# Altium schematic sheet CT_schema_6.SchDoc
size 405 x 220 mm
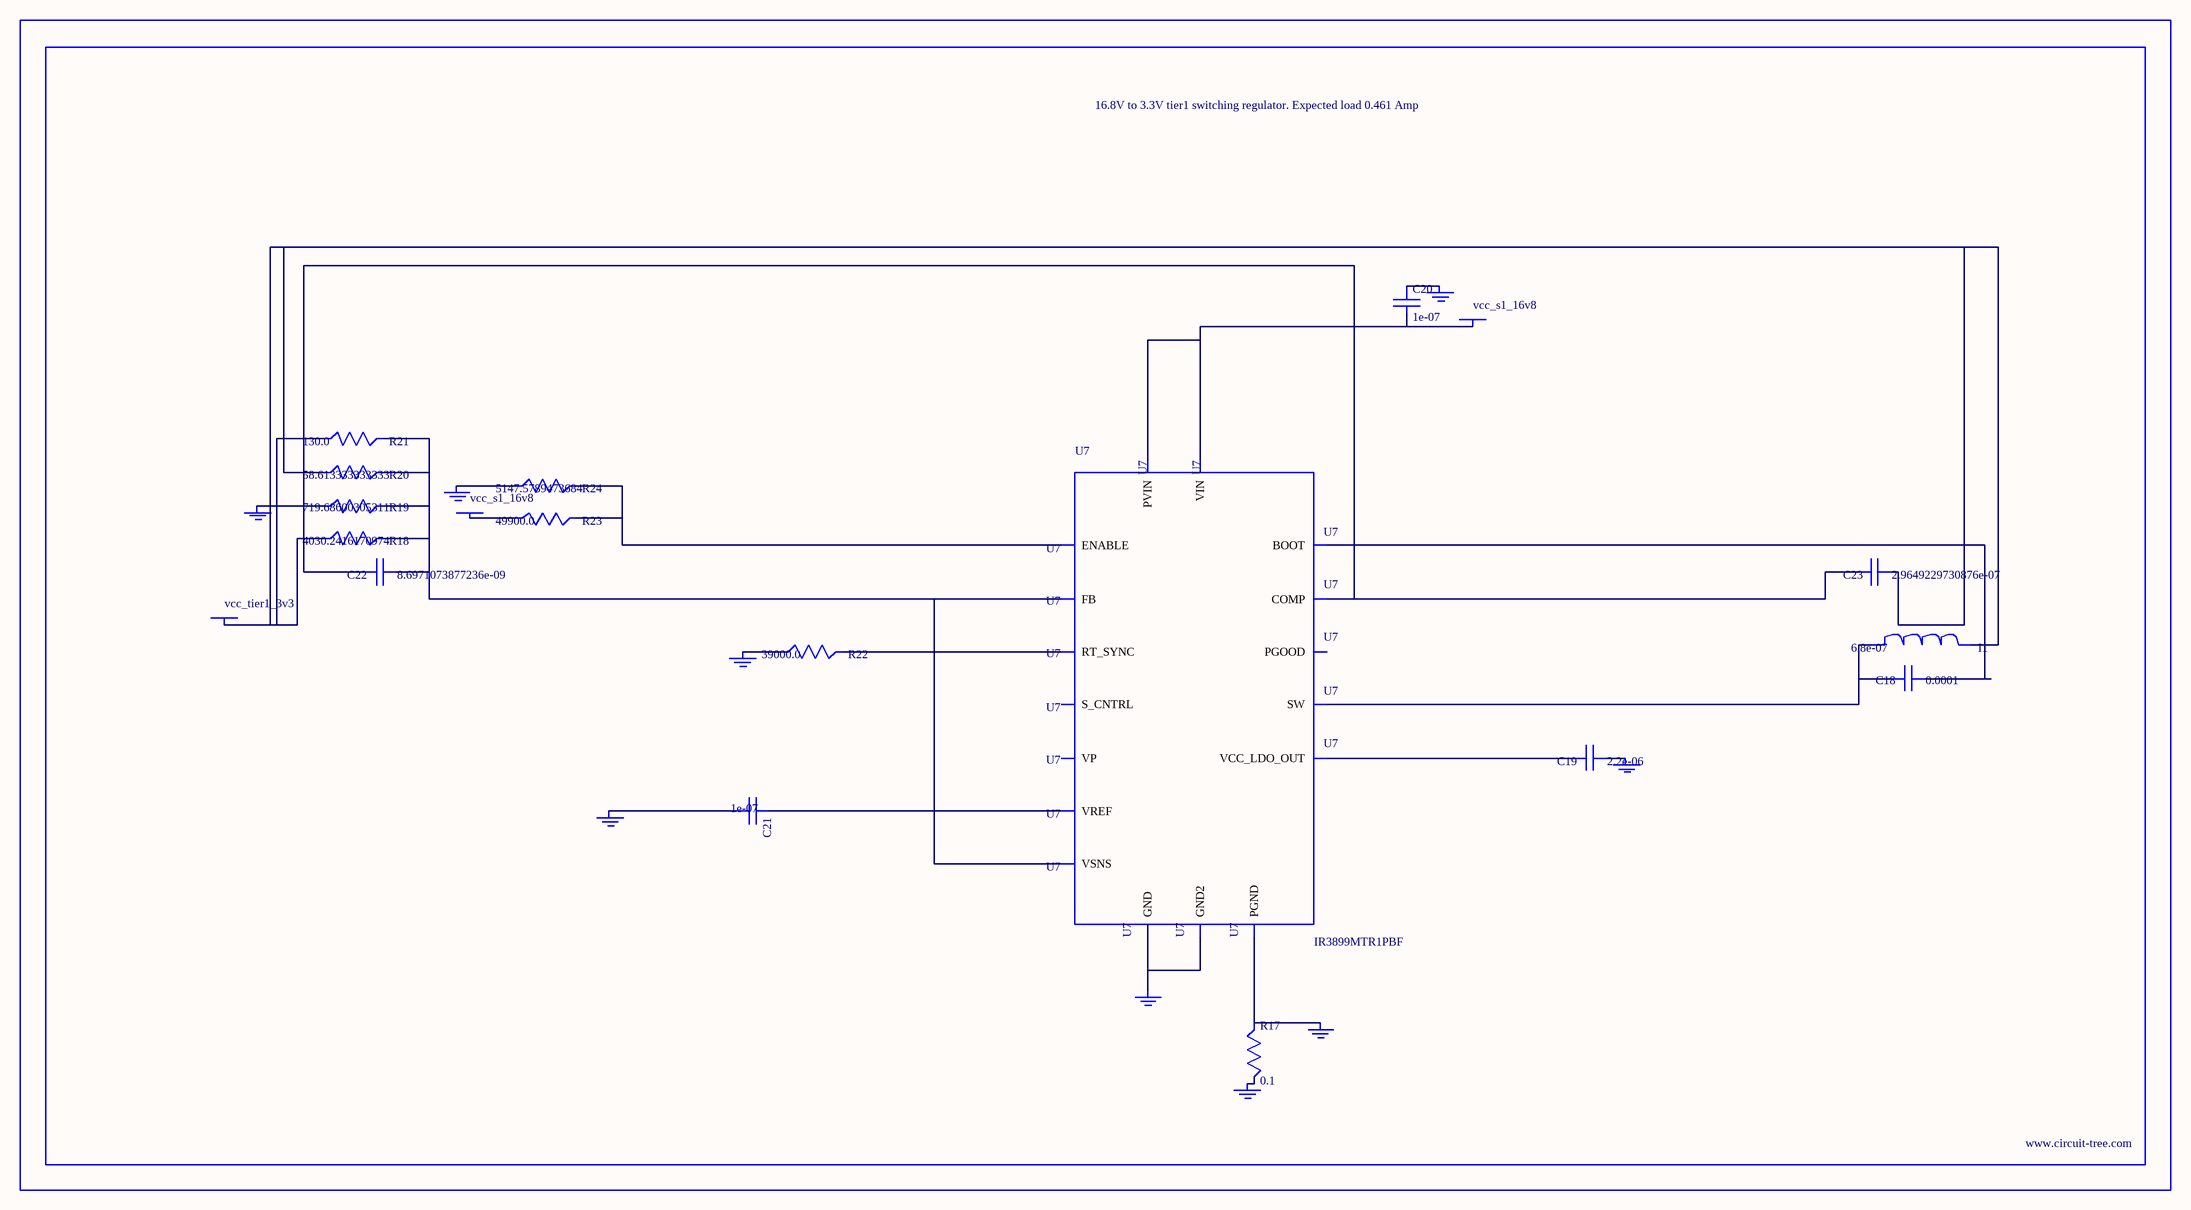
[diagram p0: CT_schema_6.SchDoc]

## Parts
BORDER5  (no value)
C18  0.0001  [C1210]
C19  2.2e-06  [C0603]
C20  1e-07  [C0402]
C21  1e-07  [C0402]
C22  8.6971073877236e-09  [R0603]
C23  2.9649229730876e-07  [R0603]
GND_INSTANCE_5_0  (no value)
GND_INSTANCE_5_1  (no value)
GND_INSTANCE_5_2  (no value)
GND_INSTANCE_5_3  (no value)
GND_INSTANCE_5_4  (no value)
GND_INSTANCE_5_5  (no value)
GND_INSTANCE_5_6  (no value)
GND_INSTANCE_5_7  (no value)
GND_INSTANCE_5_8  (no value)
I1  6.8e-07  [IND25X25CZ]
POWER_INSTANCE_5_0  vcc_s1_16v8
POWER_INSTANCE_5_1  vcc_s1_16v8
POWER_INSTANCE_5_2  vcc_tier1_3v3
R17  0.1  [R0603]
R18  4030.2416170974  [R0603]
R19  719.68600305311  [R0603]
R20  58.613333333333  [R0603]
R21  130.0  [R0603]
R22  39000.0  [R0603]
R23  49900.0  [R0603]
R24  5147.5789473684  [R0603]
U7  IR3899MTR1PBF  [IR3899MTR1PBF]

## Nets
NetC18_1: C18.1 U7.14(BOOT)
NetC18_2: C18.2 I1.1 U7.12(SW)
NetC19_1: C19.1 GND_INSTANCE_5_4.0(GND)
NetC19_2: C19.2 U7.10(VCC_LDO_OUT)
NetC20_1: C20.1 GND_INSTANCE_5_3.0(GND)
NetC20_2: C20.2 POWER_INSTANCE_5_0.0(PWR) U7.9(VIN) U7.13(PVIN)
NetC21_1: C21.1 U7.2(VREF)
NetC21_2: C21.2 GND_INSTANCE_5_1.0(GND)
NetC22_1: C22.1 R18.2 R19.2 R20.2 R21.2 U7.1(FB) U7.8(VSNS)
NetC22_2: C22.2 C23.2 U7.3(COMP)
NetC23_1: C23.1 I1.2 POWER_INSTANCE_5_2.0(PWR) R18.1 R20.1 R21.1
NetGND_INSTANCE_5_0_0: GND_INSTANCE_5_0.0(GND) R19.1
NetGND_INSTANCE_5_2_0: GND_INSTANCE_5_2.0(GND) R22.1
NetGND_INSTANCE_5_5_0: GND_INSTANCE_5_5.0(GND) R17.2
NetGND_INSTANCE_5_6_0: GND_INSTANCE_5_6.0(GND) R17.1 U7.11(PGND)
NetGND_INSTANCE_5_7_0: GND_INSTANCE_5_7.0(GND) R24.1
NetGND_INSTANCE_5_8_0: GND_INSTANCE_5_8.0(GND) U7.4(GND) U7.17(GND2)
NetPOWER_INSTANCE_5_1_0: POWER_INSTANCE_5_1.0(PWR) R23.1
NetR22_2: R22.2 U7.5(RT_SYNC)
NetR23_2: R23.2 R24.2 U7.15(ENABLE)

Not connected (* = marked no-connect by the designer): U7 6(S_CNTRL) 7(PGOOD) 16(VP)

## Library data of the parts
BORDER5 = BORDER_PAGE5
C18 = GRM32ER61A107ME20L
C19 = C0603C225K8RACTU
C20 C21 = C0402C104K3RACTU
C22 = C22
C23 = C23
GND_INSTANCE_5_0-GND_INSTANCE_5_8 = GND
I1 = IHLP2525CZERR68M01
POWER_INSTANCE_5_0-POWER_INSTANCE_5_2 = PWR
R17 = ERJ-3RSFR10V
R18 = R18
R19 = R19
R20 = R20
R21 = RC0603JR-07130RL
R22 = RC0603JR-0739KL
R23 = RC0603FR-0749K9
R24 = R24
